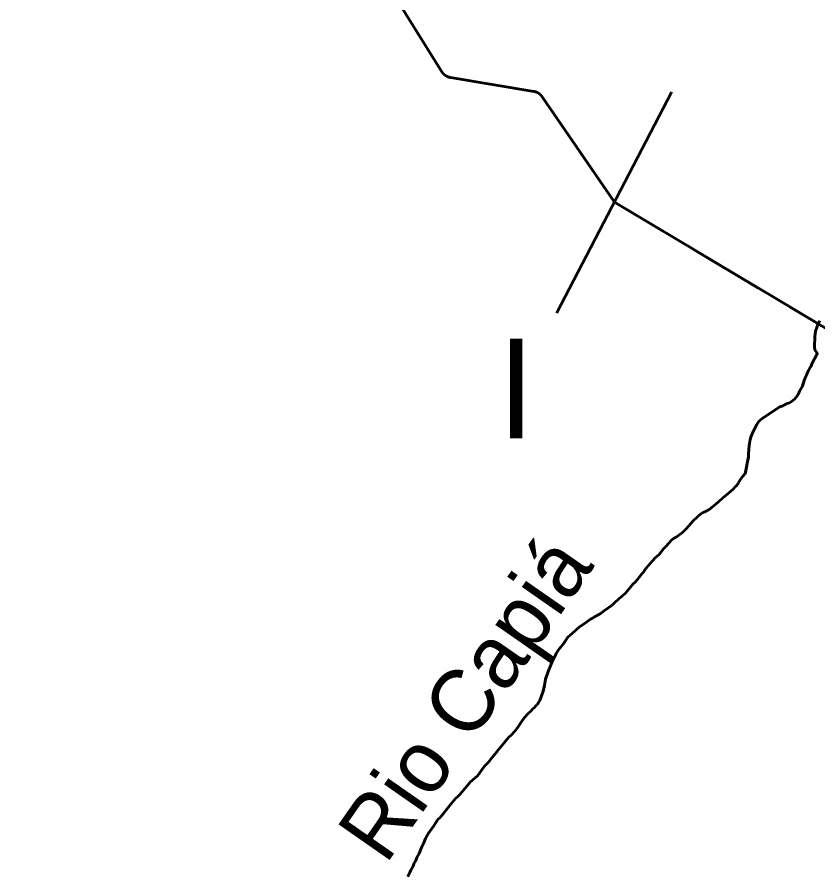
# Model space of a CAD drawing. Extents: x -1643653 to 4543381, y 1624270 to 13878484.
# Drawn here: x 645322 to 651748, y 8961468 to 8968347 of the extents above; entities that cross this region are included whole.
import ezdxf
from ezdxf.enums import TextEntityAlignment as Align

# ---------------------------------------------------------------- set-up
doc = ezdxf.new("R2010")
doc.units = 0
doc.header["$LTSCALE"] = 200
doc.linetypes.add('MEDIUM_DASHED', pattern=[4.5, 3, -1.5])
for name, color, linetype, lineweight in [('1', 7, 'Continuous', 13), ('24', 7, 'Continuous', 25), ('27', 7, 'Continuous', 53), ('31', 7, 'Continuous', 53), ('60', 7, 'Continuous', 53)]:
    doc.layers.add(name, color=color, linetype=linetype, lineweight=lineweight)
doc.layers.add('49', color=7, linetype='Continuous')

msp = doc.modelspace()

# ---------------------------------------------------------------- linework, layer by layer
at = {"layer": '1', "lineweight": 25}
msp.add_spline([(814781, 9009175.5), (814787.2, 9009173.4), (814796.9, 9009173.4), (814799.4, 9009172.4), (814805.1, 9009174.5), (814805.6, 9009176.5), (814811.7, 9009179.5), (814811.7, 9009179.5), (814801.5, 9009181), (814790.7, 9009181.5), (814784.1, 9009183.1), (814777.4, 9009185.1), (814778.4, 9009175.5)], degree=3, dxfattribs=at)
at = {"layer": '24', "lineweight": 53}
for points in [[(651759.8, 8965907.9), (651741.4, 8965863.8), (651729.4, 8965826.5), (651723.3, 8965779.3), (651720.3, 8965699.1), (651722.8, 8965675), (651743.5, 8965648.6), (651743.4, 8965644.6), (651698.9, 8965564), (651693.6, 8965544.1), (651688.2, 8965540.4), (651686.5, 8965534.9), (651674.3, 8965514.2), (651664.3, 8965494.4), (651655.9, 8965471.5), (651645.4, 8965450), (651637.1, 8965429.3), (651623.4, 8965385), (651601.4, 8965342.9), (651591.7, 8965321.5), (651577.2, 8965299.5), (651559.6, 8965280.8), (651533.4, 8965257.4), (651515.3, 8965247.1), (651499.6, 8965244.2), (651496.3, 8965241.1), (651479.6, 8965235.3), (651466.6, 8965226.9), (651443.2, 8965217.1), (651307.6, 8965130.1), (651287.6, 8965112.6), (651272.7, 8965096.7), (651258.7, 8965075.1), (651231.1, 8965023.9), (651213.3, 8964982.5), (651203.9, 8964956.5), (651195.2, 8964907.3), (651191.2, 8964841.6), (651191, 8964817.2), (651164.9, 8964678.6), (651157.3, 8964676.2), (651155.4, 8964668.4), (651148.9, 8964664.2), (651138.2, 8964651.3), (651124.9, 8964632.4), (651105.4, 8964599.6), (651094.6, 8964583.9), (651089.5, 8964580.2), (651065.3, 8964555.2), (651012.9, 8964509), (650998.5, 8964498.8), (650986.4, 8964486.1), (650949.3, 8964456), (650900.6, 8964412.3), (650874.5, 8964393.6), (650844.8, 8964377.2), (650826.4, 8964368.8), (650809.3, 8964357.4), (650785.7, 8964337.7), (650747.8, 8964302.8), (650693.7, 8964240.3), (650662, 8964208.7), (650662, 8964208.7), (650632.1, 8964188.2), (650618, 8964175.7), (650604.2, 8964169.9), (650589.6, 8964160.3)], [(650589.6, 8964160.3), (650574.3, 8964146.5), (650530.2, 8964098.3), (650509, 8964077.9), (650473.5, 8964033), (650442.6, 8964005.1), (650368.1, 8963919.8), (650346, 8963888.5), (650332.8, 8963874.9), (650310.5, 8963845.9), (650278.5, 8963808.1), (650264.2, 8963793.4), (650207.7, 8963725.5), (650176.4, 8963697.3), (650153.9, 8963678.9), (650140.4, 8963665.7), (650124.7, 8963653.2), (650103.3, 8963631.9), (650086.5, 8963618), (650072.4, 8963608.2), (650060.6, 8963597.7), (650046.6, 8963590.1), (650000.4, 8963555.6), (649955.2, 8963530.6), (649939, 8963520), (649922.4, 8963511.9), (649893.1, 8963492), (649865.1, 8963469.6), (649835.2, 8963451.3), (649777.6, 8963401.4), (649742.6, 8963367.3), (649718.9, 8963335.7), (649704, 8963312.6), (649674.6, 8963276.8), (649661.2, 8963257.8), (649648.9, 8963237.2), (649640.8, 8963219.3), (649630.7, 8963202.8), (649615, 8963169.3), (649608.8, 8963150.8), (649584.8, 8963092.3), (649563.2, 8963031.5), (649555.5, 8962980.1), (649545.2, 8962946.6), (649541.4, 8962928), (649515.6, 8962859.5), (649507.1, 8962843.2), (649499.9, 8962833.4), (649481.2, 8962814.6), (649475.3, 8962806.6), (649456.2, 8962788.3), (649449.4, 8962778.8), (649420.2, 8962753.5), (649395, 8962724.1), (649367.2, 8962685.5), (649343.5, 8962648.1), (649319.4, 8962615.6), (649289.5, 8962584.5), (649264.9, 8962562.7), (649217.7, 8962504.2), (649187.2, 8962469.5), (649162, 8962433.2), (649131.5, 8962399.3), (649105.7, 8962365.4), (649075.9, 8962335.3), (649056.5, 8962311.9), (649027.9, 8962268.9), (649013.5, 8962252.7), (648961.3, 8962205.6), (648876.1, 8962105.7), (648858.3, 8962087.9), (648839.2, 8962071.7), (648801.6, 8962026.5), (648742.1, 8961950.5), (648715.9, 8961919), (648698.4, 8961903), (648678.4, 8961875.1), (648665.1, 8961852.7), (648623.9, 8961794), (648612.1, 8961775.1), (648600.3, 8961752.7), (648585.9, 8961717.7), (648566.1, 8961679.4), (648547.4, 8961632), (648528.6, 8961598.4), (648520.4, 8961575.2), (648506.1, 8961547), (648501.5, 8961529.9), (648482.2, 8961497.1), (648474.8, 8961478.5), (648456.4, 8961445.7)]]:
    msp.add_lwpolyline(points, dxfattribs=at)
at = {"layer": '27'}
msp.add_line((651746.6, 8965885.9), (650115.3, 8966860.5), dxfattribs=at)
for points in [[(648284.2, 8968627.1), (648730.3, 8967908.7), (648730.4, 8967908.7), (648731.9, 8967906.3), (648733.5, 8967903.9), (648735.2, 8967901.7), (648736.9, 8967899.4), (648738.7, 8967897.2), (648740.5, 8967895.1), (648742.4, 8967893), (648744.4, 8967891), (648746.4, 8967889), (648748.5, 8967887.1), (648750.6, 8967885.2), (648752.8, 8967883.4), (648755, 8967881.7), (648757.3, 8967880), (648759.7, 8967878.4), (648762, 8967876.8), (648764.4, 8967875.4), (648766.9, 8967874), (648769.4, 8967872.6), (648771.9, 8967871.4), (648774.5, 8967870.2), (648777.1, 8967869.1), (648779.7, 8967868), (648782.4, 8967867.1), (648785.1, 8967866.2), (648787.8, 8967865.3), (648790.5, 8967864.6), (648793.2, 8967863.9), (648796, 8967863.3), (648798.8, 8967862.8), (649469.2, 8967750.6), (649470.5, 8967750.4), (649473.2, 8967749.9), (649476, 8967749.2), (649478.7, 8967748.6), (649481.5, 8967747.8), (649484.2, 8967746.9), (649486.8, 8967746), (649489.5, 8967745), (649492.1, 8967743.9), (649494.7, 8967742.8), (649497.2, 8967741.5), (649499.7, 8967740.2), (649502.2, 8967738.9), (649504.7, 8967737.4), (649507, 8967735.9), (649509.4, 8967734.4), (649511.7, 8967732.7)], [(649511.7, 8967732.7), (649509.4, 8967734.4), (649507, 8967735.9), (649504.7, 8967737.4), (649502.2, 8967738.9), (649499.7, 8967740.2), (649497.2, 8967741.5), (649494.7, 8967742.8), (649492.1, 8967743.9), (649489.5, 8967745), (649486.8, 8967746), (649484.2, 8967746.9), (649481.5, 8967747.8), (649478.7, 8967748.6), (649476, 8967749.2), (649473.2, 8967749.9), (649470.5, 8967750.4), (649469.2, 8967750.6), (648798.8, 8967862.8), (648796, 8967863.3), (648793.2, 8967863.9), (648790.5, 8967864.6), (648787.8, 8967865.3), (648785.1, 8967866.2), (648782.4, 8967867.1), (648779.7, 8967868), (648777.1, 8967869.1), (648774.5, 8967870.2), (648771.9, 8967871.4), (648769.4, 8967872.6), (648766.9, 8967874), (648764.4, 8967875.4), (648762, 8967876.8), (648759.7, 8967878.4), (648757.3, 8967880), (648755, 8967881.7), (648752.8, 8967883.4), (648750.6, 8967885.2), (648748.5, 8967887.1), (648746.4, 8967889), (648744.4, 8967891), (648742.4, 8967893), (648740.5, 8967895.1), (648738.7, 8967897.2), (648736.9, 8967899.4), (648735.2, 8967901.7), (648733.5, 8967903.9), (648731.9, 8967906.3), (648730.4, 8967908.7), (648730.3, 8967908.7), (648284.2, 8968627.1)], [(649511.7, 8967732.7), (649514, 8967731), (649516.2, 8967729.3), (649518.3, 8967727.4), (649520.4, 8967725.6), (649522.5, 8967723.6), (649524.5, 8967721.6), (649526.4, 8967719.5), (649528.3, 8967717.4), (649530.1, 8967715.3), (649531.9, 8967713.1), (649533.6, 8967710.8), (649535.2, 8967708.5), (650115.3, 8966860.5), (651746.6, 8965885.9)], [(650115.3, 8966860.5), (649535.2, 8967708.5), (649533.6, 8967710.8), (649531.9, 8967713.1), (649530.1, 8967715.3), (649528.3, 8967717.4), (649526.4, 8967719.5), (649524.5, 8967721.6), (649522.5, 8967723.6), (649520.4, 8967725.6), (649518.3, 8967727.4), (649516.2, 8967729.3), (649514, 8967731), (649511.7, 8967732.7)], [(650589.6, 8964160.3), (650604.2, 8964169.9), (650618, 8964175.7), (650632.1, 8964188.2), (650662, 8964208.7), (650662, 8964208.7), (650693.7, 8964240.3), (650747.8, 8964302.8), (650785.7, 8964337.7), (650809.3, 8964357.4), (650826.4, 8964368.8), (650844.8, 8964377.2), (650874.5, 8964393.6), (650900.6, 8964412.3), (650949.3, 8964456), (650986.4, 8964486.1), (650998.5, 8964498.8), (651012.9, 8964509), (651065.3, 8964555.2), (651089.5, 8964580.2), (651094.6, 8964583.9), (651105.4, 8964599.6), (651124.9, 8964632.4), (651138.2, 8964651.3), (651148.9, 8964664.2), (651155.4, 8964668.4), (651157.3, 8964676.2), (651164.9, 8964678.6), (651191, 8964817.2), (651191.2, 8964841.6), (651195.2, 8964907.3), (651203.9, 8964956.5), (651213.3, 8964982.5), (651231.1, 8965023.9), (651258.7, 8965075.1), (651272.7, 8965096.7), (651287.6, 8965112.6), (651307.6, 8965130.1), (651443.2, 8965217.1), (651466.6, 8965226.9), (651479.6, 8965235.3), (651496.3, 8965241.1), (651499.6, 8965244.2), (651515.3, 8965247.1), (651533.4, 8965257.4), (651559.6, 8965280.8), (651577.2, 8965299.5), (651591.7, 8965321.5), (651601.4, 8965342.9), (651623.4, 8965385), (651637.1, 8965429.3), (651645.4, 8965450), (651655.9, 8965471.5), (651664.3, 8965494.4), (651674.3, 8965514.2), (651686.5, 8965534.9), (651688.2, 8965540.4), (651693.6, 8965544.1), (651698.9, 8965564), (651743.4, 8965644.6), (651743.5, 8965648.6), (651722.8, 8965675), (651720.3, 8965699.1), (651723.3, 8965779.3), (651729.4, 8965826.5), (651741.4, 8965863.8), (651748.8, 8965881.5)], [(650589.6, 8964160.3), (650604.2, 8964169.9), (650618, 8964175.7), (650632.1, 8964188.2), (650662, 8964208.7), (650662, 8964208.7), (650693.7, 8964240.3), (650747.8, 8964302.8), (650785.7, 8964337.7), (650809.3, 8964357.4), (650826.4, 8964368.8), (650844.8, 8964377.2), (650874.5, 8964393.6), (650900.6, 8964412.3), (650949.3, 8964456), (650986.4, 8964486.1), (650998.5, 8964498.8), (651012.9, 8964509), (651065.3, 8964555.2), (651089.5, 8964580.2), (651094.6, 8964583.9), (651105.4, 8964599.6), (651124.9, 8964632.4), (651138.2, 8964651.3), (651148.9, 8964664.2), (651155.4, 8964668.4), (651157.3, 8964676.2), (651164.9, 8964678.6), (651191, 8964817.2), (651191.2, 8964841.6), (651195.2, 8964907.3), (651203.9, 8964956.5), (651213.3, 8964982.5), (651231.1, 8965023.9), (651258.7, 8965075.1), (651272.7, 8965096.7), (651287.6, 8965112.6), (651307.6, 8965130.1), (651443.2, 8965217.1), (651466.6, 8965226.9), (651479.6, 8965235.3), (651496.3, 8965241.1), (651499.6, 8965244.2), (651515.3, 8965247.1), (651533.4, 8965257.4), (651559.6, 8965280.8), (651577.2, 8965299.5), (651591.7, 8965321.5), (651601.4, 8965342.9), (651623.4, 8965385), (651637.1, 8965429.3), (651645.4, 8965450), (651655.9, 8965471.5), (651664.3, 8965494.4), (651674.3, 8965514.2), (651686.5, 8965534.9), (651688.2, 8965540.4), (651693.6, 8965544.1), (651698.9, 8965564), (651743.4, 8965644.6), (651743.5, 8965648.6), (651722.8, 8965675), (651720.3, 8965699.1), (651723.3, 8965779.3), (651729.4, 8965826.5), (651741.4, 8965863.8), (651748.8, 8965881.5)], [(648456.4, 8961445.7), (648474.8, 8961478.5), (648482.2, 8961497.1), (648501.5, 8961529.9), (648506.1, 8961547), (648520.4, 8961575.2), (648528.6, 8961598.4), (648547.4, 8961632), (648566.1, 8961679.4), (648585.9, 8961717.7), (648600.3, 8961752.7), (648612.1, 8961775.1), (648623.9, 8961794), (648665.1, 8961852.7), (648678.4, 8961875.1), (648698.4, 8961903), (648715.9, 8961919), (648742.1, 8961950.5), (648801.6, 8962026.5), (648839.2, 8962071.7), (648858.3, 8962087.9), (648876.1, 8962105.7), (648961.3, 8962205.6), (649013.5, 8962252.7), (649027.9, 8962268.9), (649056.5, 8962311.9), (649075.9, 8962335.3), (649105.7, 8962365.4), (649131.5, 8962399.3), (649162, 8962433.2), (649187.2, 8962469.5), (649217.7, 8962504.2), (649264.9, 8962562.7), (649289.5, 8962584.5), (649319.4, 8962615.6), (649343.5, 8962648.1), (649367.2, 8962685.5), (649395, 8962724.1), (649420.2, 8962753.5), (649449.4, 8962778.8), (649456.2, 8962788.3), (649475.3, 8962806.6), (649481.2, 8962814.6), (649499.9, 8962833.4), (649507.1, 8962843.2), (649515.6, 8962859.5), (649541.4, 8962928), (649545.2, 8962946.6), (649555.5, 8962980.1), (649563.2, 8963031.5), (649584.8, 8963092.3), (649608.8, 8963150.8), (649615, 8963169.3), (649630.7, 8963202.8), (649640.8, 8963219.3), (649648.9, 8963237.2), (649661.2, 8963257.8), (649674.6, 8963276.8), (649704, 8963312.6), (649718.9, 8963335.7), (649742.6, 8963367.3), (649777.6, 8963401.4), (649835.2, 8963451.3), (649865.1, 8963469.6), (649893.1, 8963492), (649922.4, 8963511.9), (649939, 8963520), (649955.2, 8963530.6), (650000.4, 8963555.6), (650046.6, 8963590.1), (650060.6, 8963597.7), (650072.4, 8963608.2), (650086.5, 8963618), (650103.3, 8963631.9), (650124.7, 8963653.2), (650140.4, 8963665.7), (650153.9, 8963678.9), (650176.4, 8963697.3), (650207.7, 8963725.5), (650264.2, 8963793.4), (650278.5, 8963808.1), (650310.5, 8963845.9), (650332.8, 8963874.9), (650346, 8963888.5), (650368.1, 8963919.8), (650442.6, 8964005.1), (650473.5, 8964033), (650509, 8964077.9), (650530.2, 8964098.3), (650574.3, 8964146.5), (650589.6, 8964160.3)], [(648456.4, 8961445.7), (648474.8, 8961478.5), (648482.2, 8961497.1), (648501.5, 8961529.9), (648506.1, 8961547), (648520.4, 8961575.2), (648528.6, 8961598.4), (648547.4, 8961632), (648566.1, 8961679.4), (648585.9, 8961717.7), (648600.3, 8961752.7), (648612.1, 8961775.1), (648623.9, 8961794), (648665.1, 8961852.7), (648678.4, 8961875.1), (648698.4, 8961903), (648715.9, 8961919), (648742.1, 8961950.5), (648801.6, 8962026.5), (648839.2, 8962071.7), (648858.3, 8962087.9), (648876.1, 8962105.7), (648961.3, 8962205.6), (649013.5, 8962252.7), (649027.9, 8962268.9), (649056.5, 8962311.9), (649075.9, 8962335.3), (649105.7, 8962365.4), (649131.5, 8962399.3), (649162, 8962433.2), (649187.2, 8962469.5), (649217.7, 8962504.2), (649264.9, 8962562.7), (649289.5, 8962584.5), (649319.4, 8962615.6), (649343.5, 8962648.1), (649367.2, 8962685.5), (649395, 8962724.1), (649420.2, 8962753.5), (649449.4, 8962778.8), (649456.2, 8962788.3), (649475.3, 8962806.6), (649481.2, 8962814.6), (649499.9, 8962833.4), (649507.1, 8962843.2), (649515.6, 8962859.5), (649541.4, 8962928), (649545.2, 8962946.6), (649555.5, 8962980.1), (649563.2, 8963031.5), (649584.8, 8963092.3), (649608.8, 8963150.8), (649615, 8963169.3), (649630.7, 8963202.8), (649640.8, 8963219.3), (649648.9, 8963237.2), (649661.2, 8963257.8), (649674.6, 8963276.8), (649704, 8963312.6), (649718.9, 8963335.7), (649742.6, 8963367.3), (649777.6, 8963401.4), (649835.2, 8963451.3), (649865.1, 8963469.6), (649893.1, 8963492), (649922.4, 8963511.9), (649939, 8963520), (649955.2, 8963530.6), (650000.4, 8963555.6), (650046.6, 8963590.1), (650060.6, 8963597.7), (650072.4, 8963608.2), (650086.5, 8963618), (650103.3, 8963631.9), (650124.7, 8963653.2), (650140.4, 8963665.7), (650153.9, 8963678.9), (650176.4, 8963697.3), (650207.7, 8963725.5), (650264.2, 8963793.4), (650278.5, 8963808.1), (650310.5, 8963845.9), (650332.8, 8963874.9), (650346, 8963888.5), (650368.1, 8963919.8), (650442.6, 8964005.1), (650473.5, 8964033), (650509, 8964077.9), (650530.2, 8964098.3), (650574.3, 8964146.5), (650589.6, 8964160.3)]]:
    msp.add_lwpolyline(points, dxfattribs=at)
at = {"layer": '31'}
msp.add_line((649653.7, 8965973.5), (650576.8, 8967747.6), dxfattribs=at)
at = {"layer": '60', "linetype": 'MEDIUM_DASHED', "lineweight": 60}
msp.add_line((652814.4, 8965247.9), (650115.3, 8966860.5), dxfattribs=at)
at = {"layer": '60'}
for points in [[(649511.7, 8967732.7), (649509.4, 8967734.4), (649507, 8967735.9), (649504.7, 8967737.4), (649502.2, 8967738.9), (649499.7, 8967740.2), (649497.2, 8967741.5), (649494.7, 8967742.8), (649492.1, 8967743.9), (649489.5, 8967745), (649486.8, 8967746), (649484.2, 8967746.9), (649481.5, 8967747.8), (649478.7, 8967748.6), (649476, 8967749.2), (649473.2, 8967749.9), (649470.5, 8967750.4), (649469.2, 8967750.6), (648798.8, 8967862.8), (648796, 8967863.3), (648793.2, 8967863.9), (648790.5, 8967864.6), (648787.8, 8967865.3), (648785.1, 8967866.2), (648782.4, 8967867.1), (648779.7, 8967868), (648777.1, 8967869.1), (648774.5, 8967870.2), (648771.9, 8967871.4), (648769.4, 8967872.6), (648766.9, 8967874), (648764.4, 8967875.4), (648762, 8967876.8), (648759.7, 8967878.4), (648757.3, 8967880), (648755, 8967881.7), (648752.8, 8967883.4), (648750.6, 8967885.2), (648748.5, 8967887.1), (648746.4, 8967889), (648744.4, 8967891), (648742.4, 8967893), (648740.5, 8967895.1), (648738.7, 8967897.2), (648736.9, 8967899.4), (648735.2, 8967901.7), (648733.5, 8967903.9), (648731.9, 8967906.3), (648730.4, 8967908.7), (648730.3, 8967908.7), (648284.2, 8968627.1)], [(650115.3, 8966860.5), (649535.2, 8967708.5), (649533.6, 8967710.8), (649531.9, 8967713.1), (649530.1, 8967715.3), (649528.3, 8967717.4), (649526.4, 8967719.5), (649524.5, 8967721.6), (649522.5, 8967723.6), (649520.4, 8967725.6), (649518.3, 8967727.4), (649516.2, 8967729.3), (649514, 8967731), (649511.7, 8967732.7)]]:
    msp.add_lwpolyline(points, dxfattribs=at)

# ---------------------------------------------------------------- texts
at = {"layer": '31'}
msp.add_text('I', height=800, dxfattribs=at).set_placement((649177.5, 8964965.7))
at = {"layer": '49'}
msp.add_text('Rio Capiá', height=500, rotation=55.114, dxfattribs=at).set_placement((649119.7, 8962738.4), align=Align.CENTER)

doc.saveas('drawing.dxf')
